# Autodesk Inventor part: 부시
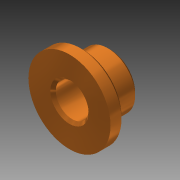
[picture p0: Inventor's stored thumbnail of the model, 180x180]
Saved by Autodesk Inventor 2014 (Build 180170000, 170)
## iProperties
Created: 2016-02
Part Number: 부시
Material: 스테인리스강
Document SubType Name: Modeling
Designer: mduedu
Density: 8.08 g/cm^3
Mass: 39.4553 g
Surface Area: 27.3717 cm^2
Volume: 4.88308 cm^3
Appearance: 금속 1600F 열
Author: mduedu
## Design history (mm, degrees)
sketch "스케치1"
  geometry: C1 r 15 at (0, 0); 1 further point
  constraints: 1 centre point, 1 coincident
  dimensions: "d0" = 30 diameter of C1
extrude "돌출1" new body sketch "스케치1" distance "d1" = 5; taper "d2" = 0 deg
sketch "스케치2"
  geometry: C1 r 10 at (0, 0); 1 further point
  constraints: 1 centre point, 1 coincident
  dimensions: "d3" = 20 diameter of C1
extrude "돌출2" join sketch "스케치2" distance "d4" = 10; taper "d5" = 0 deg
hole "구멍1" diameter "d8" = 12; stored, may be unused: countersink angle "d12" = 90 deg, drill point angle "d14" = 118 deg; dims "d9" = 6, "d10" = 4, "d11" = 2, "d13" = 8, "d15" = 10, "d16" = 10
chamfer "모따기1" distance "d17" = 1; stored, may be unused: second distance "d18" = 2, angle "d19" = 45 deg
chamfer "모따기2" distance "d20" = 1; stored, may be unused: second distance "d21" = 2, angle "d22" = 45 deg
chamfer "모따기3" distance "d23" = 1; stored, may be unused: second distance "d24" = 2, angle "d25" = 45 deg
node "솔리드1"
